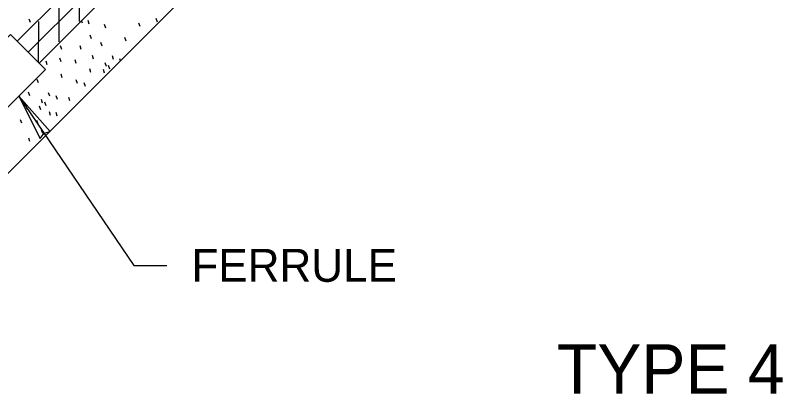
# Model space of a CAD drawing. Extents: x 99861 to 103151, y 100000 to 102076.
# Drawn here: x 101740.1 to 102112.9, y 101502.2 to 101686.1 of the extents above; entities that cross this region are included whole.
import ezdxf

# ---------------------------------------------------------------- set-up
doc = ezdxf.new("R2010")
doc.units = 0
for name, color, linetype in [('Level 1', 7, 'Continuous'), ('Level 15', 7, 'Continuous'), ('Level 18', 7, 'Continuous'), ('Level 2', 7, 'Continuous'), ('Level 20', 7, 'Continuous'), ('Level 4', 7, 'Continuous'), ('Level 6', 7, 'Continuous'), ('Level 8', 7, 'Continuous')]:
    doc.layers.add(name, color=color, linetype=linetype)

msp = doc.modelspace()

# ---------------------------------------------------------------- linework, layer by layer
at = {"layer": 'Level 1'}
for p, q in [((101740.93, 101673.54), (101824.97, 101757.64)), ((101835.76, 101746.85), (101751.59, 101662.88)), ((101751.59, 101662.88), (101740.93, 101673.54))]:
    msp.add_line(p, q, dxfattribs=at)
at = {"layer": 'Level 15'}
for p, q in [((101741.76, 101646.81), (101797.64, 101564.57)), ((101797.64, 101564.57), (101813.64, 101564.57))]:
    msp.add_line(p, q, dxfattribs=at)
msp.add_lwpolyline([(101741.76, 101646.81), (101752.12, 101626.25), (101754, 101628.8), (101757.06, 101629.6)], close=True, dxfattribs=at)
at = {"layer": 'Level 2'}
msp.add_line((101854.86, 101727.74), (101707.23, 101580.01), dxfattribs=at)
at = {"layer": 'Level 4'}
for p, q in [((101949.09, 101870.5), (101746.29, 101668.19)), ((101771.08, 101702.81), (101771.06, 101683.01)), ((101761.17, 101692.93), (101761.15, 101673.13)), ((101751.26, 101683.04), (101751.24, 101663.24))]:
    msp.add_line(p, q, dxfattribs=at)
at = {"layer": 'Level 6'}
for p, q in [((101737.79, 101676.72), (101754.72, 101659.71)), ((101754.72, 101659.71), (101714.14, 101619.32))]:
    msp.add_line(p, q, dxfattribs=at)
msp.add_lwpolyline([(101697.21, 101636.33), (101714.14, 101619.32), (101754.72, 101659.71), (101737.79, 101676.72), (101697.21, 101636.33)], dxfattribs=at)
at = {"layer": 'Level 8'}
for p, q in [((101809.08, 101682.72), (101808.5, 101684.46)), ((101747.36, 101682.51), (101746.79, 101684.25)), ((101772.68, 101682.21), (101772.26, 101683.51)), ((101775.96, 101681.78), (101775.39, 101683.52)), ((101784.03, 101679.86), (101783.46, 101681.61)), ((101800.65, 101680.56), (101800.08, 101682.3)), ((101777.04, 101674.67), (101776.47, 101676.41)), ((101793.87, 101673.55), (101793.29, 101675.29)), ((101762.64, 101669.45), (101762.07, 101671.19)), ((101772.1, 101669.49), (101771.53, 101671.24)), ((101782.25, 101671.1), (101781.68, 101672.84)), ((101778.08, 101664.82), (101777.51, 101666.57)), ((101787.8, 101664.63), (101787.22, 101666.37)), ((101755.57, 101661.97), (101755, 101663.71)), ((101762.32, 101663.43), (101761.75, 101665.18)), ((101769.65, 101662.66), (101769.08, 101664.41)), ((101784.3, 101661.25), (101783.73, 101663)), ((101791.19, 101664.03), (101790.92, 101664.88)), ((101776.82, 101658.29), (101776.25, 101660.04)), ((101783.45, 101658.03), (101782.88, 101659.78)), ((101785.98, 101659.95), (101785.4, 101661.7)), ((101751.25, 101653.2), (101750.68, 101654.95)), ((101762.87, 101655.65), (101762.3, 101657.4)), ((101770.24, 101652.94), (101769.67, 101654.69)), ((101774.16, 101651.51), (101773.59, 101653.26)), ((101747.09, 101646.93), (101746.51, 101648.67)), ((101756.8, 101646.73), (101756.23, 101648.48)), ((101753.3, 101643.36), (101752.73, 101645.1)), ((101754.98, 101642.05), (101754.41, 101643.8)), ((101760.49, 101645.24), (101759.92, 101646.98)), ((101766.63, 101644.45), (101766.06, 101646.2)), ((101745.83, 101640.4), (101745.26, 101642.14)), ((101752.46, 101640.14), (101751.88, 101641.88)), ((101757.19, 101637.46), (101756.62, 101639.2)), ((101760.47, 101637.03), (101759.9, 101638.77)), ((101743.17, 101633.61), (101742.59, 101635.36)), ((101751.15, 101633.19), (101750.57, 101634.94)), ((101753.43, 101628.61), (101752.86, 101630.35)), ((101747.15, 101624.7), (101746.58, 101626.44))]:
    msp.add_line(p, q, dxfattribs=at)

# ---------------------------------------------------------------- texts
at = {"layer": 'Level 18'}
msp.add_text('TYPE 4', height=24, dxfattribs=at).set_placement((102003.24, 101502.21))
at = {"layer": 'Level 20'}
msp.add_text('FERRULE', height=16, dxfattribs=at).set_placement((101825.64, 101556.57))

doc.saveas('drawing.dxf')
